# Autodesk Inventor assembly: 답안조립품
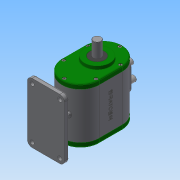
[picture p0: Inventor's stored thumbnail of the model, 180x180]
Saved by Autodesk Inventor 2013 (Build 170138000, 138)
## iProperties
Created: 2018-10
Part Number: 답안조립품
Document SubType Name: Assembly
Designer: Administrator
Author: Administrator
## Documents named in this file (15)
- C:\Users\Administrator\Desktop\381007V1024\답안조립품.iam
- C:\Users\Administrator\Desktop\381007V1024\뒤커버.ipt
- C:\Users\Administrator\Desktop\381007V1024\메인축.ipt
- C:\Users\Administrator\Desktop\381007V1024\베어링 608.ipt
- C:\Users\Administrator\Desktop\381007V1024\베어링 6003.ipt
- C:\Users\Administrator\Desktop\381007V1024\본체.ipt
- C:\Users\Administrator\Desktop\381007V1024\볼트 M4.ipt
- C:\Users\Administrator\Desktop\381007V1024\부시.ipt
- C:\Users\Administrator\Desktop\381007V1024\서브축.ipt
- C:\Users\Administrator\Desktop\381007V1024\슬라이더.ipt
- C:\Users\Administrator\Desktop\381007V1024\앞커버.ipt
- C:\Users\Administrator\Desktop\381007V1024\오일실 8 22 7.ipt
- C:\Users\Administrator\Desktop\381007V1024\오일실 17 32 8.ipt
- C:\Users\Administrator\Desktop\381007V1024\가변스프링1.ipt
- C:\Users\Administrator\Desktop\381007V1024\가변스프링2.ipt
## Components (2 placed, 2 different names)
1. 가변스프링1:1
2. 가변스프링2:1
